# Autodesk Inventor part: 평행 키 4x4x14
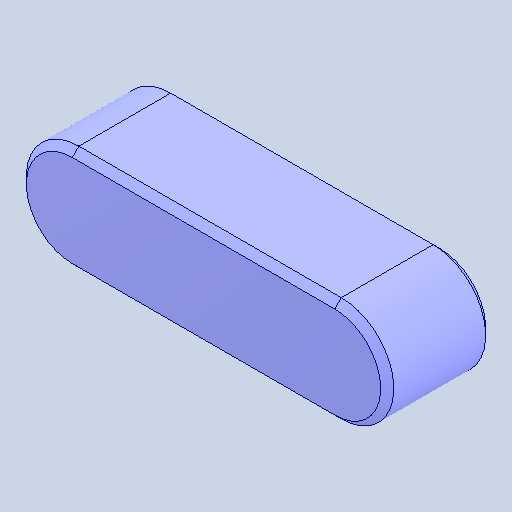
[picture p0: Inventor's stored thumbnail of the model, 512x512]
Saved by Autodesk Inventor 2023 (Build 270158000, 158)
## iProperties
Created: 2026-06
Part Number: 평행 키 4x4x14
Material: 강철, 연강
Description: 키 및 해당 키홈
Document SubType Name: Modeling
Designer: 4강의실
Density: 7.85 g/cm^3
Appearance: 기본값
Author: jhkim
Sending System: Autodesk Inventor 2027
Preprocessor: ST-DEVELOPER v20.1
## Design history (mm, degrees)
feature "Solid1"
node "솔리드1"
